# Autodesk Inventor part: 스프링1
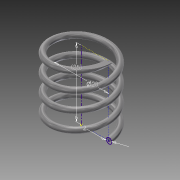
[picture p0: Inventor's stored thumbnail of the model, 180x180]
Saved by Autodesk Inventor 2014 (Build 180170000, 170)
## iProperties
Created: 2016-07
Part Number: 스프링1
Material: 스테인레스 스틸
Document SubType Name: Modeling
Designer: owner
Density: 8.08 g/cm^3
Appearance: 반연마
Author: owner
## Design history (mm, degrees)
sketch "스케치1"
  geometry: L1 (-10, 0)-(0, 0); L2 (0, 0)-(0, 22.5); L3 (0, 22.5)-(-10, 22.5); L4 (-10, 22.5)-(-10, 0); C1 r 1 at (-10, 0); 1 further point
  constraints: 8 end point, 2 coincident, 2 parallel, 1 centre point, 1 horizontal, 1 perpendicular
  dimensions: "d0" = 2 diameter of C1; "d1" = 22.5 distance of L1.end L2.end (derived); "d2" = 20 diameter of L4 L2
feature "코일1" sketch "스케치1" pitch "d3" = 10; turns "d5" = 4; dims "d4" = 22.5 (= d1), "d6" = 0, angle "d7" = 90 deg, angle "d8" = 90 deg, "d9" = 0, "d10" = 0
node "작업 평면1"
sketch "스케치2"
  geometry: L1 (0, 0)-(2, 0) reference; 1 further point
  constraints: 1 horizontal alignment
extrude "돌출1" cut sketch "스케치2" distance "d11" = 10; taper "d12" = 0 deg
node "작업 평면2"
sketch "스케치3"
  geometry: L1 (0, 0)-(-2, 0) reference; 1 further point
  constraints: 1 horizontal alignment
extrude "돌출2" cut sketch "스케치3" distance "d13" = 10; taper "d14" = 0 deg
node "솔리드1"
node "절단 모서리 투영1"
node "절단 모서리 투영2"
